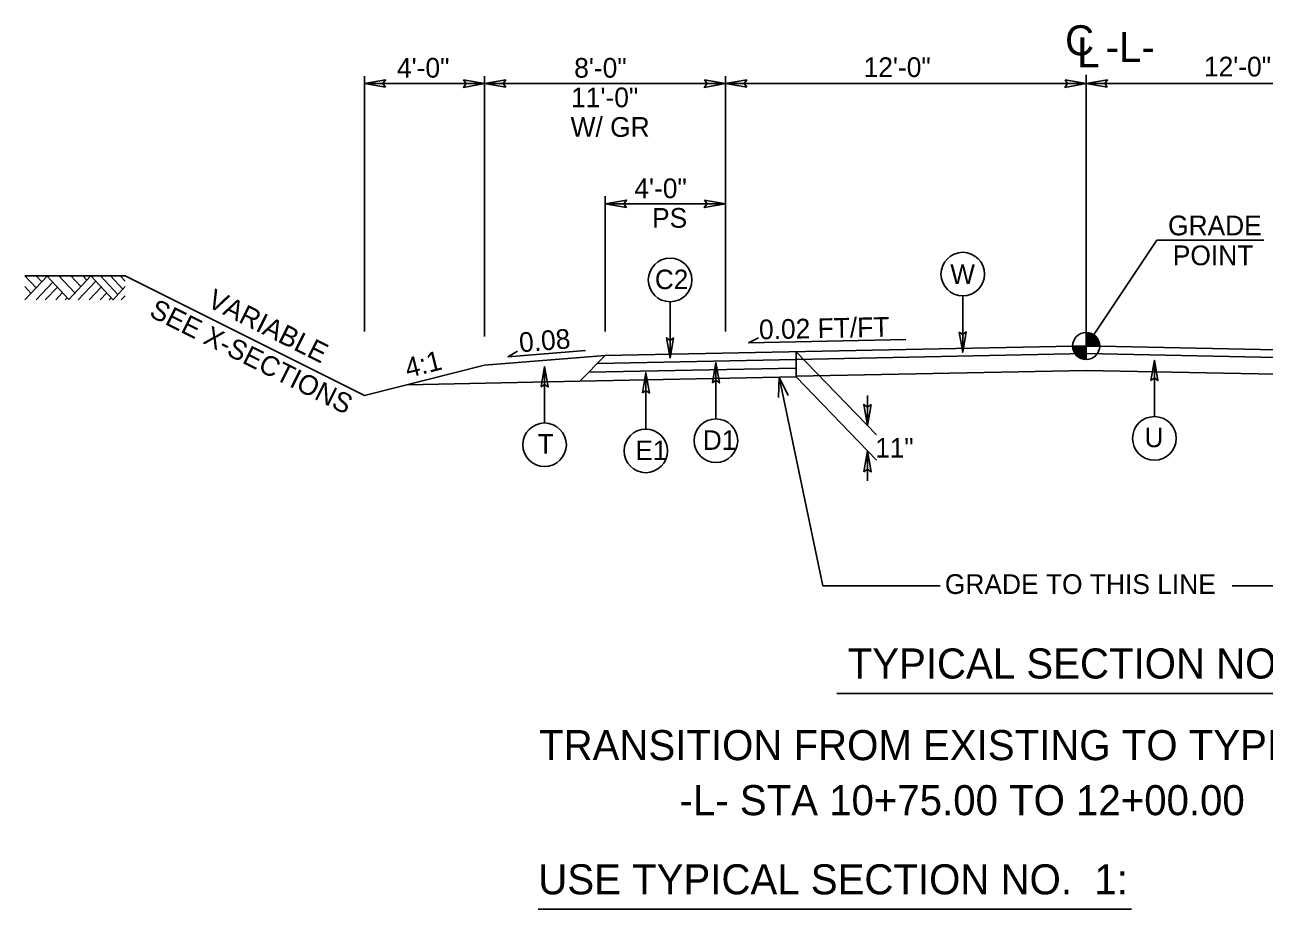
# Model space of a CAD drawing. Extents: x 1901984 to 1902132, y 194049 to 194156.
# Drawn here: x 1901984.24 to 1902025.49, y 194127.02 to 194156.44 of the extents above; entities that cross this region are included whole.
import ezdxf

# ---------------------------------------------------------------- set-up
doc = ezdxf.new("R2010")
doc.units = 0
for name, color, linetype in [('Old_Level_1', 7, 'Continuous'), ('Old_Level_11', 7, 'Continuous'), ('Old_Level_2', 7, 'Continuous'), ('Old_Level_20', 7, 'Continuous'), ('Old_Level_3', 7, 'Continuous'), ('Scratch_Level_3', 7, 'Continuous')]:
    doc.layers.add(name, color=color, linetype=linetype)

# ---------------------------------------------------------------- blocks, each defined once
blk = doc.blocks.new('TERMINATOR')
at = {"layer": 'Scratch_Level_3'}
blk.add_lwpolyline([(-0.469, 0.081), (0, 0), (-0.471, -0.083), (-0.411, 0)], close=True, dxfattribs=at)

msp = doc.modelspace()

# ---------------------------------------------------------------- linework, layer by layer
at = {"layer": 'Old_Level_1'}
for p, q in [((1901995.543, 194146.236), (1901995.543, 194154.736)), ((1901999.543, 194146.074), (1901999.543, 194154.736)), ((1902007.561, 194146.236), (1902007.561, 194154.736)), ((1902019.561, 194145.756), (1902019.561, 194154.776)), ((1901995.543, 194154.486), (1901999.543, 194154.486)), ((1901999.543, 194154.486), (1902007.561, 194154.486)), ((1902007.561, 194154.486), (1902019.561, 194154.486)), ((1902031.561, 194154.486), (1902019.561, 194154.486)), ((1902003.561, 194146.236), (1902003.561, 194150.736)), ((1902003.561, 194150.486), (1902007.561, 194150.486)), ((1901987.586, 194148.093), (1901995.543, 194144.114)), ((1902008.326, 194145.858), (1902008.659, 194146.025)), ((1902013.558, 194145.968), (1902008.326, 194145.858)), ((1902019.561, 194145.756), (1902019.561, 194146.206)), ((1902003.561, 194145.436), (1901999.543, 194145.114)), ((1902002.898, 194145.603), (1902000.318, 194145.396)), ((1902000.318, 194145.396), (1902000.64, 194145.583)), ((1902003.561, 194145.436), (1902002.711, 194144.585)), ((1902018.561, 194145.736), (1902003.561, 194145.436)), ((1902009.906, 194145.562), (1902009.906, 194144.729)), ((1902009.906, 194145.562), (1902012.584, 194142.796)), ((1902019.565, 194145.506), (1902009.906, 194145.312)), ((1902019.561, 194145.756), (1902018.561, 194145.736)), ((1902019.111, 194145.756), (1902019.561, 194145.756)), ((1902019.56, 194145.306), (1902019.561, 194145.756)), ((1902019.561, 194145.756), (1902019.56, 194145.306)), ((1902020.011, 194145.756), (1902019.561, 194145.756)), ((1902019.561, 194145.756), (1902020.561, 194145.736)), ((1902019.565, 194145.505), (1902029.22, 194145.312)), ((1902020.561, 194145.736), (1902035.561, 194145.436)), ((1901999.543, 194145.114), (1901995.543, 194144.114)), ((1902009.902, 194145.021), (1902003.009, 194144.883)), ((1902009.906, 194145.312), (1902003.306, 194145.18)), ((1902009.906, 194144.729), (1902002.711, 194144.585)), ((1902009.346, 194144.718), (1902010.799, 194137.776)), ((1902019.576, 194144.944), (1902009.906, 194144.75)), ((1902009.906, 194144.729), (1902012.584, 194141.962)), ((1902019.55, 194144.944), (1902029.211, 194144.75)), ((1902002.711, 194144.585), (1901996.968, 194144.47)), ((1902012.282, 194144.108), (1902012.282, 194143.108)), ((1902012.282, 194142.274), (1902012.282, 194141.274)), ((1902010.799, 194137.776), (1902014.708, 194137.776)), ((1902024.414, 194137.776), (1902028.323, 194137.776))]:
    msp.add_line(p, q, dxfattribs=at)
for points in [[(1901984.244, 194148.093), (1901987.586, 194148.093)], [(1902019.565, 194146.206), (1902019.565, 194146.206), (1902019.565, 194145.756)], [(1902019.574, 194146.206), (1902019.574, 194145.756)], [(1902019.583, 194146.205), (1902019.583, 194145.756)], [(1902019.592, 194146.205), (1902019.592, 194145.756)], [(1902019.601, 194146.204), (1902019.601, 194145.756)], [(1902019.61, 194146.203), (1902019.61, 194145.756)], [(1902019.619, 194146.202), (1902019.619, 194145.756)], [(1902019.628, 194146.201), (1902019.628, 194145.756)], [(1902019.637, 194146.2), (1902019.637, 194145.756)], [(1902019.646, 194146.198), (1902019.646, 194145.756)], [(1902019.655, 194146.196), (1902019.655, 194145.756)], [(1902019.664, 194146.194), (1902019.664, 194145.756)], [(1902019.673, 194146.192), (1902019.673, 194145.756)], [(1902019.682, 194146.189), (1902019.682, 194145.756)], [(1902019.691, 194146.187), (1902019.691, 194145.756)], [(1902019.7, 194146.184), (1902019.7, 194145.756)], [(1902019.709, 194146.181), (1902019.709, 194145.756)], [(1902019.718, 194146.178), (1902019.718, 194145.756)], [(1902019.727, 194146.174), (1902019.727, 194145.756)], [(1902019.736, 194146.17), (1902019.736, 194145.756)], [(1902019.745, 194146.166), (1902019.745, 194145.756)], [(1902019.754, 194146.162), (1902019.754, 194145.756)], [(1902019.763, 194146.158), (1902019.763, 194145.756)], [(1902019.772, 194146.153), (1902019.772, 194145.756)], [(1902019.781, 194146.148), (1902019.781, 194145.756)], [(1902019.79, 194146.143), (1902019.79, 194145.756)], [(1902019.799, 194146.138), (1902019.799, 194145.756)], [(1902019.808, 194146.132), (1902019.808, 194145.756)], [(1902019.817, 194146.126), (1902019.817, 194145.756)], [(1902019.826, 194146.119), (1902019.826, 194145.756)], [(1902019.835, 194146.113), (1902019.835, 194145.756)], [(1902019.844, 194146.106), (1902019.844, 194145.756)], [(1902019.853, 194146.098), (1902019.853, 194145.756)], [(1902019.862, 194146.09), (1902019.862, 194145.756)], [(1902019.871, 194146.082), (1902019.871, 194145.756)], [(1902019.88, 194146.073), (1902019.88, 194145.756)], [(1902019.889, 194146.064), (1902019.889, 194145.756)], [(1902019.898, 194146.054), (1902019.898, 194145.756)], [(1902019.907, 194146.043), (1902019.907, 194145.756)], [(1902019.916, 194146.032), (1902019.916, 194145.756)], [(1902019.925, 194146.02), (1902019.925, 194145.756)], [(1902019.934, 194146.007), (1902019.934, 194145.756)], [(1902019.943, 194145.993), (1902019.943, 194145.756)], [(1902019.952, 194145.978), (1902019.952, 194145.756)], [(1902019.961, 194145.962), (1902019.961, 194145.756)], [(1902019.97, 194145.943), (1902019.97, 194145.756)], [(1902019.979, 194145.922), (1902019.979, 194145.756)], [(1902019.988, 194145.897), (1902019.988, 194145.756)], [(1902019.997, 194145.866), (1902019.997, 194145.756)], [(1902019.113, 194145.756), (1902019.113, 194145.707)], [(1902019.122, 194145.756), (1902019.122, 194145.654)], [(1902019.131, 194145.756), (1902019.131, 194145.622)], [(1902019.14, 194145.756), (1902019.14, 194145.595)], [(1902019.149, 194145.756), (1902019.149, 194145.574)], [(1902019.158, 194145.756), (1902019.158, 194145.555)], [(1902019.167, 194145.756), (1902019.167, 194145.538)], [(1902019.176, 194145.756), (1902019.176, 194145.522)], [(1902019.185, 194145.756), (1902019.185, 194145.508)], [(1902019.194, 194145.756), (1902019.194, 194145.495)], [(1902019.203, 194145.756), (1902019.203, 194145.483)], [(1902019.212, 194145.756), (1902019.212, 194145.472)], [(1902019.221, 194145.756), (1902019.221, 194145.461)], [(1902019.23, 194145.756), (1902019.23, 194145.451)], [(1902019.239, 194145.756), (1902019.239, 194145.441)], [(1902019.248, 194145.756), (1902019.248, 194145.432)], [(1902019.257, 194145.756), (1902019.257, 194145.424)], [(1902019.266, 194145.756), (1902019.266, 194145.416)], [(1902019.275, 194145.756), (1902019.275, 194145.408)], [(1902019.284, 194145.756), (1902019.284, 194145.401)], [(1902019.293, 194145.756), (1902019.293, 194145.394)], [(1902019.302, 194145.756), (1902019.302, 194145.388)], [(1902019.311, 194145.756), (1902019.311, 194145.382)], [(1902019.32, 194145.756), (1902019.32, 194145.376)], [(1902019.329, 194145.756), (1902019.329, 194145.37)], [(1902019.338, 194145.756), (1902019.338, 194145.365)], [(1902019.347, 194145.756), (1902019.347, 194145.36)], [(1902019.356, 194145.756), (1902019.356, 194145.355)], [(1902019.365, 194145.756), (1902019.365, 194145.351)], [(1902019.374, 194145.756), (1902019.374, 194145.347)], [(1902019.383, 194145.756), (1902019.383, 194145.343)], [(1902019.392, 194145.756), (1902019.392, 194145.339)], [(1902019.401, 194145.756), (1902019.401, 194145.335)], [(1902019.41, 194145.756), (1902019.41, 194145.332)], [(1902019.419, 194145.756), (1902019.419, 194145.329)], [(1902019.428, 194145.756), (1902019.428, 194145.326)], [(1902019.437, 194145.756), (1902019.437, 194145.324)], [(1902019.446, 194145.756), (1902019.446, 194145.321)], [(1902019.455, 194145.756), (1902019.455, 194145.319)], [(1902019.464, 194145.756), (1902019.464, 194145.317)], [(1902019.473, 194145.756), (1902019.473, 194145.315)], [(1902019.482, 194145.756), (1902019.482, 194145.313)], [(1902019.491, 194145.756), (1902019.491, 194145.312)], [(1902019.5, 194145.756), (1902019.5, 194145.31)], [(1902019.509, 194145.756), (1902019.509, 194145.309)], [(1902019.518, 194145.756), (1902019.518, 194145.308)], [(1902019.527, 194145.756), (1902019.527, 194145.307)], [(1902019.536, 194145.756), (1902019.536, 194145.307)], [(1902019.545, 194145.756), (1902019.545, 194145.306)], [(1902019.554, 194145.756), (1902019.554, 194145.306), (1902019.554, 194145.306)], [(1902020.006, 194145.82), (1902020.006, 194145.756)], [(1902009.64, 194144.109), (1902009.346, 194144.718), (1902009.319, 194144.042)]]:
    msp.add_lwpolyline(points, dxfattribs=at)
msp.add_circle((1902019.56, 194145.756), 0.45, dxfattribs=at)
for start, end in [(359.9905, 89.9905), (179.9905, 269.9905)]:
    msp.add_arc((1902019.56, 194145.756), 0.45, start, end, dxfattribs=at)
at = {"layer": 'Old_Level_11'}
for p, q in [((1901984.244, 194148.093), (1901984.619, 194147.69)), ((1901984.244, 194147.288), (1901984.986, 194148.085)), ((1901984.619, 194148.093), (1901984.806, 194147.892)), ((1901984.986, 194148.085), (1901985.71, 194147.306)), ((1901985.377, 194148.093), (1901985.91, 194147.52)), ((1901985.71, 194147.306), (1901986.441, 194148.092)), ((1901985.775, 194148.093), (1901986.108, 194147.734)), ((1901986.02, 194147.288), (1901986.606, 194147.916)), ((1901986.177, 194148.093), (1901986.31, 194147.95)), ((1901986.441, 194148.092), (1901987.182, 194147.296)), ((1901986.763, 194148.093), (1901987.343, 194147.47)), ((1901987.096, 194148.093), (1901987.51, 194147.649)), ((1901987.416, 194148.093), (1901987.586, 194147.91)), ((1901984.244, 194147.731), (1901984.45, 194147.509)), ((1901984.618, 194147.288), (1901985.172, 194147.884)), ((1901984.927, 194147.288), (1901985.328, 194147.717)), ((1901985.274, 194147.288), (1901985.501, 194147.531)), ((1901986.39, 194147.288), (1901986.79, 194147.717)), ((1901986.756, 194147.288), (1901986.973, 194147.521)), ((1901987.182, 194147.296), (1901987.586, 194147.731)), ((1901985.585, 194147.288), (1901985.656, 194147.364)), ((1901987.051, 194147.288), (1901987.12, 194147.362)), ((1901987.452, 194147.288), (1901987.586, 194147.431)), ((1902005.717, 194147.229), (1902005.717, 194145.355)), ((1902015.453, 194147.424), (1902015.453, 194145.55)), ((1902001.539, 194143.196), (1902001.539, 194145.07)), ((1902007.24, 194143.331), (1902007.24, 194145.205)), ((1902021.831, 194143.409), (1902021.831, 194145.284)), ((1902004.908, 194142.992), (1902004.908, 194144.867)), ((1902011.269, 194134.201), (1902027.895, 194134.201)), ((1902001.331, 194127.021), (1902021.074, 194127.021))]:
    msp.add_line(p, q, dxfattribs=at)
for points in [[(1902005.833, 194146.027), (1902005.717, 194145.355), (1902005.598, 194146.03), (1902005.717, 194145.944)], [(1902015.338, 194146.221), (1902015.453, 194145.55), (1902015.573, 194146.225), (1902015.453, 194146.139)], [(1902001.423, 194144.399), (1902001.539, 194145.07), (1902001.658, 194144.395), (1902001.539, 194144.481)], [(1902007.124, 194144.534), (1902007.24, 194145.205), (1902007.359, 194144.53), (1902007.24, 194144.616)], [(1902021.715, 194144.612), (1902021.831, 194145.284), (1902021.95, 194144.608), (1902021.831, 194144.694)], [(1902004.793, 194144.195), (1902004.908, 194144.867), (1902005.028, 194144.191), (1902004.908, 194144.277)]]:
    msp.add_lwpolyline(points, close=True, dxfattribs=at)
for centre in [(1902015.454, 194148.149), (1902005.717, 194147.954), (1902021.831, 194142.684), (1902001.539, 194142.471), (1902004.908, 194142.267), (1902007.24, 194142.606)]:
    msp.add_circle(centre, 0.725, dxfattribs=at)
at = {"layer": 'Old_Level_3'}
for q in [(1902019.561, 194145.756), (1902025.476, 194149.28)]:
    msp.add_line((1902021.912, 194149.28), q, dxfattribs=at)

# ---------------------------------------------------------------- block references
at = {"layer": 'Old_Level_1', "xscale": 1.5, "yscale": 1.5}
for p, rotation in [((1901995.543, 194154.486), 180), ((1901999.543, 194154.486), 180), ((1902007.561, 194154.486), 180), ((1902019.561, 194154.486), 180), ((1902003.561, 194150.486), 180), ((1902012.282, 194143.108), -90), ((1902012.282, 194142.274), 90)]:
    msp.add_blockref('TERMINATOR', p, dxfattribs=dict(at, rotation=rotation))
for p in [(1901999.543, 194154.486), (1902007.561, 194154.486), (1902019.561, 194154.486), (1902007.561, 194150.486)]:
    msp.add_blockref('TERMINATOR', p, dxfattribs=at)

# ---------------------------------------------------------------- texts
at = {"layer": 'Old_Level_1'}
for s, p in [('4\'-0" ', (1901996.628, 194154.684)), ('12\'-0" ', (1902012.155, 194154.704)), ('12\'-0" ', (1902023.479, 194154.724)), ('GRADE TO THIS LINE', (1902014.859, 194137.508))]:
    msp.add_text(s, height=0.656, dxfattribs=at).set_placement(p)
for s, rotation, p in [('8\'-0"', 360, (1902002.525, 194154.683)), ('11\'-0"', 360, (1902002.423, 194153.699)), ('W/ GR', 360, (1902002.406, 194152.715)), ('4\'-0"', 360, (1902004.526, 194150.674)), ('PS', 360, (1902005.116, 194149.69)), ('VARIABLE', 333.4349, (1901990.275, 194147.089)), ('SEE X-SECTIONS', 333.4349, (1901988.349, 194146.759)), ('4:1', 14.0362, (1901996.988, 194144.689))]:
    msp.add_text(s, height=0.656, rotation=rotation, dxfattribs=at).set_placement(p)
at = {"layer": 'Old_Level_11'}
for s, height, p in [('GRADE', 0.656, (1902022.285, 194149.438)), ('POINT', 0.656, (1902022.443, 194148.444)), ('TYPICAL SECTION NO.  1', 1, (1902011.625, 194134.695)), ('TRANSITION FROM EXISTING TO TYPICAL SECTION NO.  1:', 1, (1902001.355, 194131.979)), ('-L- STA 10+75.00 TO 12+00.00', 1, (1902006.031, 194130.148)), ('USE TYPICAL SECTION NO.  1:', 1, (1902001.331, 194127.515))]:
    msp.add_text(s, height=height, dxfattribs=at).set_placement(p)
at = {"layer": 'Old_Level_2'}
msp.add_text('C', height=1, dxfattribs=at).set_placement((1902018.859, 194155.427))
for s, height, rotation, p in [('-L-', 1, 359.9469, (1902020.21, 194155.206)), ('L', 1, 359.9469, (1902019.261, 194155.023)), ('0.02 FT/FT', 0.656, 1.1916, (1902008.681, 194145.977)), ('0.08', 0.656, 4.5739, (1902000.718, 194145.545))]:
    msp.add_text(s, height=height, rotation=rotation, dxfattribs=at).set_placement(p)
at = {"layer": 'Old_Level_20'}
for s, height, p in [('C2', 0.6491, (1902005.211, 194147.648)), ('W', 0.649, (1902015.04, 194147.821)), ('D1', 0.6491, (1902006.807, 194142.302)), ('U', 0.649, (1902021.503, 194142.391)), ('T', 0.649, (1902001.311, 194142.178)), ('E1', 0.6491, (1902004.563, 194141.963)), ('11"', 0.6491, (1902012.544, 194142.044))]:
    msp.add_text(s, height=height, dxfattribs=at).set_placement(p)

doc.saveas('drawing.dxf')
